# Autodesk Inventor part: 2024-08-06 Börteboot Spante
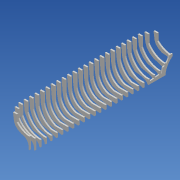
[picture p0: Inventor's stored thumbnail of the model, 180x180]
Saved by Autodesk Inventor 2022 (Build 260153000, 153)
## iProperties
Created: 2024-08
Part Number: 2024-08-06 Börteboot Spante
Material: Generisch
Document SubType Name: Modeling
Designer: i3meg
Density: 1 g/cm^3
Appearance: Vorgabe
Author: i3meg
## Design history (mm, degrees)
sketch "Skizze3"
  geometry: L1 (-117.6, 0)-(19.6, 0) reference; L2 (0, -36.667)-(0, 220.005) reference; L3 (-4, 12)-(-4, 0); L4 (0, 0)-(0, 30); L5 (-35, 30)-(0, 30); L6 (-62, 23)-(-78, 41); L7 (-78, 41)-(-86, 62); L8 (-86, 62)-(-90, 83); L9 (-90, 130)-(-78, 130); L10 (-90, 83)-(-90, 130); L11 (-98, 115)-(-98, 105); L12 (-98, 105)-(-90, 105); L13 (-98, 115)-(-78, 115); L14 (-78, 130)-(-78, 90); L15 (-4, 0)-(0, 0); L16 (-4, 12)-(0, 12); L17 (-90, 83)-(-94, 130); L18 (-94, 130)-(-90, 130); A1 r 59.222 centre (-18.855, 86.979) between (-78, 90) and (-35, 30); A2 r 171.355 centre (-1.548, 183.337) between (-62, 23) and (-4, 12)
  constraints: 34 end point, 5 point on line, 4 perpendicular, 4 point on circle, 3 vertical, 2 centre point, 2 horizontal
  dimensions: "d283" = 4 distance between parallel lines of L2 L3; "d514" = 90 distance from line of L2 L8.end; "d519" = 130 distance from line of L1 L9.start; "d527" = 12 distance of L9.start L9.end; "d538" = 10 distance of L11.start L11.end; "d545" = 35 distance from line of L2 L5.start; "d1072" = 83 distance from line of L1 L8.end; "d1132" = 15 distance between parallel lines of L9 L13; "d1133" = 40 distance of L9.end L14.end; "d1134" = 8 distance between parallel lines of L10 L11; "d1143" = 22 distance from line of L12 L8.end (derived); "d1144" = 86 distance from line of L2 L7.end; "d1145" = 78 distance from line of L2 L6.end; "d1146" = 62 distance from line of L2 L6.start; "d1245" = 21 vertical distance of L8.end L7.end; "d1246" = 21 vertical distance of L7.end L6.end; "d1247" = 18 vertical distance of L6.end L6.start; "d1452" = 4 distance of L9.start L17.end
extrude "Extrusion11" new body sketch "Skizze3" stored distance "d616" = 6; taper "d617" = 0 deg
pattern_linear "Rechteckige Anordnung3" dims "d675" = 23
workplane "Arbeitsebene5"
sketch "Skizze25"
  geometry: L1 (-60, -6)-(-77, 12); L2 (-77, 12)-(-85.5, 33); L3 (-35, 0)-(0, 0); L4 (-85.5, 33)-(-90, 54); L5 (-98, 75)-(-90, 75); L6 (-98, 85)-(-98, 75); L7 (-98, 85)-(-82, 85); L8 (-90, 100)-(-78, 100); L9 (-90, 54)-(-90, 100); L10 (-78, 100)-(-78, 60); L11 (-4, -18)-(-4, -30); L12 (-4, -30)-(0, -30); L13 (0, -30)-(0, 0); L14 (-4, -18)-(0, -18); L15 (-122.858, -30)-(51.151, -30) reference; L16 (0, -88.006)-(0, 318.037) reference; L17 (-90, 54)-(-94, 100); L18 (-94, 100)-(-90, 100); A1 r 66.906 centre (-11.141, 62.507) between (-78, 60) and (-35, 0); A2 r 279.676 centre (26.292, 260.031) between (-60, -6) and (-4, -18)
  constraints: 34 end point, 4 point on circle, 4 point on line, 3 vertical, 2 centre point, 2 horizontal, 2 perpendicular
  dimensions: "d1150" = 12 distance of L8.start L8.end; "d1151" = 10 distance of L6.start L5.start; "d1152" = 15 distance between parallel lines of L8 L7; "d1153" = 40 distance of L8.end L10.end; "d1154" = 8 distance between parallel lines of L9 L6; "d1157" = 77 distance from line of L16 L1.end; "d1158" = 85.5 distance from line of L16 L2.end; "d1159" = 90 distance from line of L16 L4.end; "d1160" = 4 distance between parallel lines of L13 L11; "d1161" = 30 distance between parallel lines of L15 L3; "d1162" = 18 distance between parallel lines of L14 L3; "d1165" = 84 distance from line of L15 L4.end; "d1239" = 35 distance from line of L13 L3.start; "d1241" = 21 vertical distance of L2.end L4.end; "d1242" = 21 vertical distance of L2.end L1.end; "d1243" = 18 vertical distance of L1.start L1.end; "d1244" = 130 distance between parallel lines of L15 L8; "d1453" = 4 distance of L17.end L8.start; "d2116" = 60 distance from line of L16 L1.start
extrude "Extrusion24" join sketch "Skizze25" distance "d1163" = 6; taper "d1164" = 0 deg
workplane "Arbeitsebene14"
sketch "Skizze26"
  geometry: L1 (-85, 34)-(-90, 55); L2 (-76, 14)-(-85, 34); L3 (-60, -4)-(-76, 14); L4 (-30, 0)-(0, 0); L5 (-98, 85)-(-98, 75); L6 (-4, -18)-(0, -18); L7 (-4, -18)-(-4, -30); L8 (-4, -30)-(0, -30); L9 (0, -30)-(0, 0); L10 (-90, 100)-(-78, 100); L11 (-78, 100)-(-78, 60); L12 (-90, 55)-(-90, 100); L13 (-98, 75)-(-90, 75); L14 (-98, 85)-(-82, 85); L15 (-132.187, -30)-(107.122, -30) reference; L16 (0, -117.748)-(0, 496.487) reference; L17 (-90, 55)-(-94, 100); L18 (-94, 100)-(-90, 100); A1 r 433.619 centre (72.935, 408.739) between (-60, -4) and (-4, -18); A2 r 81.932 centre (2.509, 75.207) between (-78, 60) and (-30, 0)
  constraints: 34 end point, 4 point on circle, 4 point on line, 3 vertical, 2 centre point, 2 horizontal, 2 perpendicular
  dimensions: "d1170" = 12 distance of L10.start L10.end; "d1171" = 10 distance of L5.start L5.end; "d1172" = 15 distance between parallel lines of L10 L14; "d1173" = 40 distance of L10.end L11.end; "d1174" = 8 distance between parallel lines of L12 L5; "d1176" = 4 distance between parallel lines of L9 L7; "d1177" = 18 distance between parallel lines of L6 L4; "d1178" = 30 distance from line of L15 L4.end; "d1180" = 76 distance from line of L16 L2.start; "d1181" = 85 distance from line of L16 L1.start; "d1182" = 90 distance from line of L16 L1.end; "d1183" = 130 distance between parallel lines of L15 L10; "d1185" = 30 distance of L4.start L4.end; "d1186" = 45 distance of L10.start L1.end; "d1248" = 21 vertical distance of L1.end L1.start; "d1249" = 20 vertical distance of L2.start L1.start; "d1250" = 18 vertical distance of L3.start L2.start; "d1251" = 60 distance from line of L16 L3.start; "d1454" = 4 distance of L17.end L10.start
extrude "Extrusion25" join sketch "Skizze26" distance "d1190" = 6; taper "d1191" = 0 deg
workplane "Arbeitsebene17"
sketch "Skizze30"
  geometry: L1 (-84.5, 36)-(-90, 56); L2 (-74, 16)-(-84.5, 36); L3 (-59, -1)-(-74, 16); L4 (-24, 1)-(0, 1); L5 (-98, 85)-(-98, 75); L6 (-4, -18)-(0, -18); L7 (-4, -18)-(-4, -30); L8 (-4, -30)-(0, -30); L9 (0, -30)-(0, 1); L10 (-90, 100)-(-78, 100); L11 (-78, 100)-(-78, 60); L12 (-90, 56)-(-90, 100); L13 (-98, 75)-(-90, 75); L14 (-98, 85)-(-82, 85); L15 (-117.95, -30)-(21.701, -30) reference; L16 (0, -281.22)-(0, 163.537) reference; L17 (-90, 56)-(-94, 100); L18 (-94, 100)-(-90, 100); A1 r 81.932 centre (1.751, 78.781) between (-78, 60) and (-24, 1); A2 r 219.794 centre (-95.847, -217.683) between (-4, -18) and (-59, -1)
  constraints: 34 end point, 4 point on circle, 3 vertical, 2 centre point, 2 perpendicular, 2 point on line, 1 horizontal
  dimensions: "d1279" = 12 distance of L10.start L10.end; "d1280" = 10 distance of L5.start L5.end; "d1281" = 15 distance between parallel lines of L10 L14; "d1282" = 40 distance of L10.end L11.end; "d1283" = 8 distance between parallel lines of L12 L5; "d1284" = 4 distance between parallel lines of L9 L7; "d1285" = 19 distance between parallel lines of L6 L4; "d1291" = 24 distance of L4.start L4.end; "d1292" = 44 distance of L10.start L1.end; "d1293" = 20 vertical distance of L1.end L1.start; "d1294" = 20 vertical distance of L2.start L1.start; "d1295" = 17 vertical distance of L3.start L2.start; "d1298" = 130 distance between parallel lines of L15 L10; "d1345" = 90 distance between parallel lines of L16 L12; "d1346" = 31 distance between parallel lines of L15 L4; "d1423" = 59 distance from line of L16 L3.start; "d1455" = 4 distance of L17.end L10.start; "d1475" = 84.5 distance from line of L16 L1.start; "d2117" = 74 distance from line of L16 L2.start
extrude "Extrusion30" join sketch "Skizze30" distance "d1300" = 6; taper "d1301" = 0 deg
workplane "Arbeitsebene18"
sketch "Skizze31"
  geometry: L1 (-84, 38)-(-90, 57); L2 (-73, 19)-(-84, 38); L3 (-58, 3)-(-73, 19); L4 (-15, 2)-(0, 2); L5 (-98, 85)-(-98, 75); L6 (-4, -18)-(0, -18); L7 (-4, -18)-(-4, -30); L8 (-4, -30)-(0, -30); L9 (0, -30)-(0, 2); L10 (-90, 100)-(-78, 100); L11 (-78, 100)-(-78, 60); L12 (-90, 57)-(-90, 100); L13 (-98, 75)-(-90, 75); L14 (-98, 85)-(-82, 85); L15 (-117.763, -30)-(20.576, -30) reference; L16 (0, -56)-(0, 126) reference; L17 (-58, 3)-(-29.474, -1); L18 (-29.474, -1)-(-10, -4); L19 (-10, -4)-(-4, -18); L20 (-90, 57)-(-94, 100); L21 (-94, 100)-(-90, 100); A1 r 81.932 centre (0.813, 82.392) between (-78, 60) and (-15, 2)
  constraints: 34 end point, 3 vertical, 2 horizontal, 2 perpendicular, 2 point on circle, 2 point on line, 1 centre point, 3 other
  dimensions: "d1303" = 12 distance of L10.start L10.end; "d1304" = 10 distance of L5.start L5.end; "d1305" = 15 distance between parallel lines of L10 L14; "d1306" = 40 distance of L10.end L11.end; "d1307" = 8 distance between parallel lines of L12 L5; "d1308" = 4 distance between parallel lines of L9 L7; "d1309" = 20 distance between parallel lines of L6 L4; "d1311" = 43 distance of L10.start L1.end; "d1318" = 90 distance between parallel lines of L16 L12; "d1319" = 32 distance between parallel lines of L15 L4; "d1320" = 130 distance between parallel lines of L15 L10; "d1421" = 10 distance from line of L16 L18.end; "d1422" = 26 distance from line of L15 L18.end; "d1458" = 4 distance of L20.end L10.start; "d1471" = 19 vertical distance of L2.start L1.start; "d1472" = 19 vertical distance of L1.start L1.end; "d1473" = 16 vertical distance of L2.start L3.start; "d2101" = 84 distance from line of L16 L1.start; "d2114" = 58 distance from line of L16 L3.start; "d2115" = 73 distance from line of L16 L2.start
extrude "Extrusion31" join sketch "Skizze31" distance "d1321" = 6; taper "d1322" = 0 deg
workplane "Arbeitsebene19"
sketch "Skizze32"
  geometry: L1 (-83, 40)-(-90, 58); L2 (-72, 22)-(-83, 40); L3 (-55, 7)-(-72, 22); L4 (-10, 6)-(0, 6); L5 (-98, 85)-(-98, 75); L6 (-4, -18)-(0, -18); L7 (-4, -18)-(-4, -30); L8 (-4, -30)-(0, -30); L9 (0, -30)-(0, 6); L10 (-90, 100)-(-78, 100); L11 (-78, 100)-(-78, 60); L12 (-90, 58)-(-90, 100); L13 (-98, 75)-(-90, 75); L14 (-98, 85)-(-82, 85); L15 (-117.674, -30)-(20.044, -30) reference; L16 (0, -56)-(0, 126) reference; L17 (-55, 7)-(-13, -2.108); L18 (-13, -2.108)-(-7, -2); L19 (-7, -2)-(-4, -18); L20 (-90, 58)-(-94, 100); L21 (-94, 100)-(-90, 100); A1 r 81.932 centre (-0.79, 87.413) between (-78, 60) and (-10, 6)
  constraints: 34 end point, 3 vertical, 2 horizontal, 2 perpendicular, 2 point on circle, 2 point on line, 1 centre point, 3 other
  dimensions: "d1324" = 12 distance of L10.start L10.end; "d1325" = 10 distance of L5.start L5.end; "d1326" = 15 distance between parallel lines of L10 L14; "d1327" = 40 distance of L10.end L11.end; "d1328" = 8 distance between parallel lines of L12 L5; "d1329" = 4 distance between parallel lines of L9 L7; "d1330" = 24 distance between parallel lines of L6 L4; "d1331" = 10 distance of L4.start L4.end; "d1332" = 42 distance of L10.start L1.end; "d1339" = 36 distance between parallel lines of L15 L4; "d1341" = 130 distance between parallel lines of L15 L10; "d1407" = 7 distance from line of L9 L18.end; "d1408" = 28 distance from line of L15 L18.end; "d1409" = 13 distance from line of L16 L17.end; "d1413" = 72 distance from line of L16 L2.start; "d1414" = 18 vertical distance of L1.start L1.end; "d1415" = 18 vertical distance of L2.start L1.start; "d1416" = 15 vertical distance of L3.start L2.start; "d1420" = 83 distance from line of L16 L1.start; "d1459" = 4 distance of L20.end L10.start; "d2102" = 90 distance between parallel lines of L16 L12
extrude "Extrusion32" join sketch "Skizze32" distance "d1342" = 6; taper "d1343" = 0 deg
workplane "Arbeitsebene20"
sketch "Skizze33"
  geometry: L1 (-82, 43)-(-88, 61); L2 (-70, 26)-(-82, 43); L3 (-52, 12)-(-70, 26); L4 (-10, 10)-(0, 10); L5 (-96, 85)-(-96, 75); L6 (-4, -8)-(0, -8); L7 (-4, -8)-(-4, -30); L8 (-4, -30)-(0, -30); L9 (0, -30)-(0, 10); L10 (-88, 100)-(-76, 100); L11 (-76, 100)-(-76, 60); L12 (-88, 61)-(-88, 100); L13 (-96, 75)-(-88, 75); L14 (-96, 85)-(-82, 85); L15 (-115.2, -30)-(19.2, -30) reference; L16 (0, -56)-(0, 126) reference; L17 (-52, 12)-(-20, 5); L18 (-20, 5)-(-7, 0); L19 (-7, 0)-(-4, -8); L20 (-88, 61)-(-92, 100); L21 (-92, 100)-(-88, 100); A1 r 81.932 centre (-0.305, 91.357) between (-76, 60) and (-10, 10); 1 further point
  constraints: 34 end point, 3 point on line, 3 vertical, 2 horizontal, 2 perpendicular, 2 point on circle, 1 centre point, 3 other
  dimensions: "d1348" = 12 distance of L10.start L10.end; "d1349" = 10 distance of L5.start L5.end; "d1350" = 15 distance between parallel lines of L10 L14; "d1351" = 40 distance of L10.end L11.end; "d1352" = 8 distance between parallel lines of L12 L5; "d1353" = 4 distance between parallel lines of L9 L7; "d1354" = 18 distance between parallel lines of L6 L4; "d1355" = 10 distance of L4.start L4.end; "d1356" = 39 distance of L10.start L1.end; "d1357" = 18 vertical distance of L1.end L1.start; "d1358" = 17 vertical distance of L2.start L1.start; "d1364" = 40 distance between parallel lines of L15 L4; "d1365" = 130 distance between parallel lines of L15 L10; "d1396" = 14 vertical distance of L2.start L3.start; "d1399" = 88 distance between parallel lines of L12 L16; "d1402" = 7 distance from line of L9 L18.end; "d1403" = 30 distance from line of L15 L18.end; "d1410" = 35 distance from line of L15 L17.end; "d1411" = 20 distance from line of L16 L17.end; "d1412" = 70 distance from line of L16 L2.start; "d1417" = 52 distance from line of L16 L3.start; "d1460" = 4 distance of L20.end L10.start; "d2118" = 82 distance from line of L16 L1.start
extrude "Extrusion33" join sketch "Skizze33" distance "d1366" = 6; taper "d1367" = 0 deg
workplane "Arbeitsebene21"
sketch "Skizze34"
  geometry: L1 (-112.834, -30)-(19.003, -30) reference; L2 (0, -57.46)-(0, 134.759) reference; L3 (-76, 48)-(-82, 65); L4 (-63.388, 33)-(-76, 48); L5 (-10, 26)-(0, 26); L6 (-90, 85)-(-90, 75); L7 (-4, 8)-(0, 8); L8 (-4, 8)-(-4, -4); L9 (-4, -4)-(0, -4); L10 (0, -4)-(0, 26); L11 (-82, 100)-(-70, 100); L12 (-70, 100)-(-70, 65); L13 (-82, 65)-(-82, 100); L14 (-90, 75)-(-82, 75); L15 (-90, 85)-(-82, 85); L16 (-4, 8)-(-6.652, 5.448); L17 (-45, 21)-(-63.388, 33); L18 (-6.652, 5.448)-(-12.18, 14.581); L19 (-12.18, 14.581)-(-45, 21); L20 (-82, 65)-(-86, 100); L21 (-86, 100)-(-82, 100); A1 r 81.932 centre (0.169, 107.299) between (-70, 65) and (-10, 26); 5 further points
  constraints: 34 end point, 3 vertical, 2 horizontal, 2 perpendicular, 2 point on circle, 2 point on line, 1 centre point, 3 other
  dimensions: "d1369" = 12 distance of L11.start L11.end; "d1370" = 10 distance of L6.start L6.end; "d1371" = 15 distance between parallel lines of L11 L15; "d1372" = 35 distance of L11.end L12.end; "d1373" = 8 distance between parallel lines of L13 L6; "d1374" = 4 distance between parallel lines of L10 L8; "d1375" = 18 distance between parallel lines of L7 L5; "d1376" = 10 distance of L5.start L5.end; "d1377" = 35 distance of L11.start L3.end; "d1378" = 17 vertical distance of L3.end L3.start; "d1379" = 15 vertical distance of L4.start L3.start; "d1384" = 82 distance between parallel lines of L2 L13; "d1385" = 56 distance between parallel lines of L1 L5; "d1386" = 130 distance between parallel lines of L1 L11; "d1451" = 12 vertical distance of L17.start L4.start; "d1461" = 4 distance of L20.end L11.start; "d1474" = 45 distance from line of L2 L17.start
extrude "Extrusion35" join sketch "Skizze34" distance "d1389" = 6; taper "d1390" = 0 deg
workplane "Arbeitsebene22"
sketch "Skizze35"
  geometry: L1 (-61.305, 57)-(-66, 70); L2 (-50.126, 46)-(-61.305, 57); L3 (-35, 38)-(-50.126, 46); L4 (-10, 47)-(0, 47); L5 (-74, 85)-(-74, 75); L6 (-4, 31)-(0, 31); L7 (-4, 31)-(-4, 15); L8 (-4, 15)-(0, 15); L9 (0, 15)-(0, 47); L10 (-66, 100)-(-54, 100); L11 (-54, 100)-(-54, 70); L12 (-66, 70)-(-66, 100); L13 (-74, 75)-(-66, 75); L14 (-74, 85)-(-82, 85); L15 (-4, 31)-(-4, 35.985); L16 (-4, 35.985)-(-12.319, 35.985); L17 (-12.319, 35.985)-(-35, 38); L18 (-66, 70)-(-70, 100); L19 (-70, 100)-(-66, 100); A1 r 81.932 centre (4.171, 127.698) between (-54, 70) and (-10, 47); 13 further points
  constraints: 35 end point, 3 vertical, 2 horizontal, 2 perpendicular, 2 point on circle, 1 centre point, 1 midpoint, 1 point on line, 5 other
  dimensions: "d1425" = 12 distance of L10.start L10.end; "d1426" = 10 distance of L5.start L5.end; "d1427" = 15 distance between parallel lines of L10 L14; "d1428" = 30 distance of L10.end L11.end; "d1429" = 8 distance between parallel lines of L12 L5; "d1430" = 4 distance between parallel lines of L9 L7; "d1431" = 16 distance between parallel lines of L6 L4; "d1432" = 10 distance of L4.start L4.end; "d1433" = 30 distance of L10.start L1.end; "d1434" = 13 vertical distance of L1.end L1.start; "d1435" = 11 vertical distance of L2.start L1.start; "d1445" = 77 dimension on L4; "d1446" = 66 distance of the line from the sketch origin of L12; "d1447" = 8 vertical distance of L2.start L3.start; "d1450" = 130 dimension on L10; "d1462" = 4 distance of L18.end L10.start; "d1970" = 35 dimension on L3.start
extrude "Extrusion36" join sketch "Skizze35" distance "d1448" = 6; taper "d1449" = 0 deg
workplane "Arbeitsebene26"
sketch "Skizze43"
  geometry: L1 (-26.579, -7)-(-43, 12); L2 (-43, 12)-(-50.5, 33); L3 (0, 0)-(35, 0); L4 (-50.5, 33)-(-55, 54); L5 (-63, 75)-(-55, 75); L6 (-63, 85)-(-63, 75); L7 (-63, 85)-(-47, 85); L8 (-55, 100)-(-43, 100); L9 (-55, 54)-(-55, 100); L10 (-43, 100)-(-43, 60); L11 (31, -18)-(31, -30); L12 (31, -30)-(35, -30); L13 (35, -30)-(35, 0); L14 (31, -18)-(35, -18); L15 (-55, 54)-(-59, 100); L16 (-59, 100)-(-55, 100); L17 (-86.48, -30)-(77.882, -30) reference; L18 (35, -88.139)-(35, 318.834) reference; A1 r 66.906 centre (23.859, 62.507) between (-43, 60) and (0, 0); A2 r 279.676 centre (54.402, 260.695) between (-26.579, -7) and (31, -18); 1 further point
  constraints: 34 end point, 4 point on circle, 3 point on line, 3 vertical, 2 centre point, 2 horizontal, 2 perpendicular
  dimensions: "d1538" = 12 distance of L8.start L8.end; "d1539" = 10 distance of L6.start L5.start; "d1540" = 15 distance between parallel lines of L8 L7; "d1541" = 40 distance of L8.end L10.end; "d1542" = 8 distance between parallel lines of L9 L6; "d1546" = 4 distance between parallel lines of L13 L11; "d1548" = 18 distance between parallel lines of L14 L3; "d1550" = 35 distance from line of L13 L3.start; "d1551" = 21 vertical distance of L2.end L4.end; "d1552" = 21 vertical distance of L2.end L1.end; "d1553" = 19 vertical distance of L1.start L1.end; "d1555" = 4 distance of L15.end L8.start; "d2103" = 90 distance between parallel lines of L18 L9; "d2104" = 85.5 distance from line of L18 L2.end; "d2119" = 78 distance from line of L18 L1.end
extrude "Extrusion41" join sketch "Skizze43" distance "d1556" = 6; taper "d1557" = 0 deg
workplane "Arbeitsebene27"
sketch "Skizze44"
  geometry: L1 (-50, 34)-(-55, 55); L2 (-42, 14)-(-50, 34); L3 (-26, -5)-(-42, 14); L4 (5, 0)-(35, 0); L5 (-63, 85)-(-63, 75); L6 (31, -18)-(35, -18); L7 (31, -18)-(31, -30); L8 (31, -30)-(35, -30); L9 (35, -30)-(35, 0); L10 (-55, 100)-(-43, 100); L11 (-43, 100)-(-43, 60); L12 (-55, 55)-(-55, 100); L13 (-63, 75)-(-55, 75); L14 (-63, 85)-(-47, 85); L15 (-55, 55)-(-59, 100); L16 (-59, 100)-(-55, 100); L17 (-95.34, -30)-(131.04, -30) reference; L18 (35, -118.06)-(35, 498.362) reference; A1 r 433.619 centre (98.7, 410.301) between (-26, -5) and (31, -18); A2 r 81.932 centre (37.509, 75.207) between (-43, 60) and (5, 0); 1 further point
  constraints: 34 end point, 4 point on circle, 3 vertical, 2 centre point, 2 horizontal, 2 perpendicular, 2 point on line
  dimensions: "d1559" = 12 distance of L10.start L10.end; "d1560" = 10 distance of L5.start L5.end; "d1561" = 15 distance between parallel lines of L10 L14; "d1562" = 40 distance of L10.end L11.end; "d1563" = 8 distance between parallel lines of L12 L5; "d1564" = 4 distance between parallel lines of L9 L7; "d1565" = 18 distance between parallel lines of L6 L4; "d1571" = 30 distance of L4.start L4.end; "d1572" = 45 distance of L10.start L1.end; "d1573" = 21 vertical distance of L1.end L1.start; "d1574" = 20 vertical distance of L2.start L1.start; "d1575" = 19 vertical distance of L3.start L2.start; "d1577" = 4 distance of L15.end L10.start; "d2105" = 90 distance between parallel lines of L18 L12; "d2106" = 85 distance from line of L18 L1.start; "d2120" = 77 distance from line of L18 L2.start
extrude "Extrusion42" join sketch "Skizze44" distance "d1578" = 6; taper "d1579" = 0 deg
workplane "Arbeitsebene28"
sketch "Skizze49"
  geometry: L1 (-49.5, 36)-(-55, 56); L2 (-40, 16)-(-49.5, 36); L3 (-25, -1)-(-40, 16); L4 (11, 1)-(35, 1); L5 (-63, 85)-(-63, 75); L6 (31, -18)-(35, -18); L7 (31, -18)-(31, -30); L8 (31, -30)-(35, -30); L9 (35, -30)-(35, 1); L10 (-55, 100)-(-43, 100); L11 (-43, 100)-(-43, 60); L12 (-55, 56)-(-55, 100); L13 (-63, 75)-(-55, 75); L14 (-63, 85)-(-47, 85); L15 (-55, 56)-(-59, 100); L16 (-59, 100)-(-55, 100); L17 (-82.95, -30)-(56.701, -30) reference; L18 (35, -281.533)-(35, 163.589) reference; A1 r 81.932 centre (36.751, 78.781) between (-43, 60) and (11, 1); A2 r 219.794 centre (-60.278, -217.944) between (31, -18) and (-25, -1); 1 further point
  constraints: 34 end point, 4 point on circle, 3 vertical, 2 centre point, 2 perpendicular, 2 point on line, 1 horizontal
  dimensions: "d1658" = 12 distance of L10.start L10.end; "d1659" = 10 distance of L5.start L5.end; "d1660" = 15 distance between parallel lines of L10 L14; "d1661" = 40 distance of L10.end L11.end; "d1662" = 8 distance between parallel lines of L12 L5; "d1663" = 4 distance between parallel lines of L9 L7; "d1664" = 19 distance between parallel lines of L6 L4; "d1665" = 24 distance of L4.start L4.end; "d1666" = 44 distance of L10.start L1.end; "d1667" = 20 vertical distance of L1.end L1.start; "d1668" = 20 vertical distance of L2.start L1.start; "d1669" = 17 vertical distance of L3.start L2.start; "d1674" = 4 distance of L15.end L10.start; "d2107" = 90 distance between parallel lines of L18 L12; "d2108" = 84.5 distance from line of L18 L1.start; "d2121" = 75 distance from line of L18 L2.start
extrude "Extrusion46" join sketch "Skizze49" distance "d1676" = 6; taper "d1677" = 0 deg
workplane "Arbeitsebene31"
sketch "Skizze51"
  geometry: L1 (-48, 38)-(-55, 57); L2 (-38, 19)-(-48, 38); L3 (-23, 3)-(-38, 19); L4 (20, 2)-(35, 2); L5 (-63, 85)-(-63, 75); L6 (31, -18)-(35, -18); L7 (31, -18)-(31, -30); L8 (31, -30)-(35, -30); L9 (35, -30)-(35, 2); L10 (-55, 100)-(-43, 100); L11 (-43, 100)-(-43, 60); L12 (-55, 57)-(-55, 100); L13 (-63, 75)-(-55, 75); L14 (-63, 85)-(-47, 85); L15 (-23, 3)-(1.526, -1); L16 (1.526, -1)-(25, -4); L17 (25, -4)-(31, -18); L18 (-55, 57)-(-59, 100); L19 (-59, 100)-(-55, 100); L20 (-82.763, -30)-(55.576, -30) reference; L21 (35, -56)-(35, 126) reference; A1 r 81.932 centre (35.813, 82.392) between (-43, 60) and (20, 2); 1 further point
  constraints: 34 end point, 3 vertical, 2 horizontal, 2 perpendicular, 2 point on circle, 2 point on line, 1 centre point, 3 other
  dimensions: "d1697" = 12 distance of L10.start L10.end; "d1698" = 10 distance of L5.start L5.end; "d1699" = 15 distance between parallel lines of L10 L14; "d1700" = 40 distance of L10.end L11.end; "d1701" = 8 distance between parallel lines of L12 L5; "d1702" = 4 distance between parallel lines of L9 L7; "d1703" = 20 distance between parallel lines of L6 L4; "d1704" = 43 distance of L10.start L1.end; "d1710" = 4 distance of L18.end L10.start; "d1711" = 19 vertical distance of L2.start L1.start; "d1712" = 19 vertical distance of L1.start L1.end; "d1713" = 16 vertical distance of L2.start L3.start; "d2109" = 90 distance between parallel lines of L21 L12; "d2110" = 83 distance from line of L21 L1.start; "d2122" = 73 distance from line of L21 L2.start
extrude "Extrusion47" join sketch "Skizze51" distance "d1714" = 6; taper "d1715" = 0 deg
workplane "Arbeitsebene32"
sketch "Skizze52"
  geometry: L1 (-46, 40)-(-55, 58); L2 (-35, 22)-(-46, 40); L3 (-20, 7)-(-35, 22); L4 (25, 6)-(35, 6); L5 (-63, 85)-(-63, 75); L6 (31, -18)-(35, -18); L7 (31, -18)-(31, -30); L8 (31, -30)-(35, -30); L9 (35, -30)-(35, 6); L10 (-55, 100)-(-43, 100); L11 (-43, 100)-(-43, 60); L12 (-55, 58)-(-55, 100); L13 (-63, 75)-(-55, 75); L14 (-63, 85)-(-47, 85); L15 (-20, 7)-(22, -2.108); L16 (22, -2.108)-(28, -2); L17 (28, -2)-(31, -18); L18 (-55, 58)-(-59, 100); L19 (-59, 100)-(-55, 100); L20 (-82.674, -30)-(55.044, -30) reference; L21 (35, -56)-(35, 126) reference; A1 r 81.932 centre (34.21, 87.413) between (-43, 60) and (25, 6); 1 further point
  constraints: 34 end point, 3 vertical, 2 horizontal, 2 perpendicular, 2 point on circle, 2 point on line, 1 centre point, 3 other
  dimensions: "d1717" = 12 distance of L10.start L10.end; "d1718" = 10 distance of L5.start L5.end; "d1719" = 15 distance between parallel lines of L10 L14; "d1720" = 40 distance of L10.end L11.end; "d1721" = 8 distance between parallel lines of L12 L5; "d1722" = 4 distance between parallel lines of L9 L7; "d1723" = 24 distance between parallel lines of L6 L4; "d1724" = 10 distance of L4.start L4.end; "d1725" = 42 distance of L10.start L1.end; "d1728" = 7 distance from line of L9 L16.end; "d1732" = 18 vertical distance of L1.start L1.end; "d1733" = 18 vertical distance of L2.start L1.start; "d1734" = 15 horizontal distance of L3.start L2.start; "d1736" = 4 distance of L18.end L10.start; "d2111" = 90 distance between parallel lines of L21 L12; "d2112" = 81 distance from line of L21 L1.start; "d2123" = 70 distance from line of L21 L2.start
extrude "Extrusion48" join sketch "Skizze52" distance "d1737" = 6; taper "d1738" = 0 deg
workplane "Arbeitsebene33"
sketch "Skizze53"
  geometry: L1 (-45, 43)-(-55, 61); L2 (-32, 26)-(-45, 43); L3 (-17, 12)-(-32, 26); L4 (25, 10)-(35, 10); L5 (-63, 85)-(-63, 75); L6 (31, -18)-(35, -18); L7 (31, -18)-(31, -30); L8 (31, -30)-(35, -30); L9 (35, -30)-(35, 10); L10 (-55, 100)-(-43, 100); L11 (-43, 100)-(-43, 60); L12 (-55, 61)-(-55, 100); L13 (-63, 75)-(-55, 75); L14 (-63, 85)-(-47, 85); L15 (-17, 12)-(15, 5); L16 (15, 5)-(28, 0); L17 (28, 0)-(31, -18); L18 (-55, 61)-(-59, 100); L19 (-59, 100)-(-55, 100); L20 (-82.91, -30)-(56.46, -30) reference; L21 (35, -56)-(35, 126) reference; A1 r 81.932 centre (32.602, 91.579) between (-43, 60) and (25, 10); 2 further points
  constraints: 34 end point, 3 vertical, 2 horizontal, 2 perpendicular, 2 point on circle, 2 point on line, 1 centre point, 3 other
  dimensions: "d1740" = 12 distance of L10.start L10.end; "d1741" = 10 distance of L5.start L5.end; "d1742" = 15 distance between parallel lines of L10 L14; "d1743" = 40 distance of L10.end L11.end; "d1744" = 8 distance between parallel lines of L12 L5; "d1745" = 4 distance between parallel lines of L9 L7; "d1746" = 28 distance between parallel lines of L6 L4; "d1747" = 10 distance of L4.start L4.end; "d1748" = 39 distance of L10.start L1.end; "d1749" = 18 vertical distance of L1.end L1.start; "d1750" = 17 vertical distance of L2.start L1.start; "d1753" = 14 vertical distance of L2.start L3.start; "d1755" = 7 distance from line of L9 L16.end; "d1761" = 4 distance of L18.end L10.start; "d2113" = 90 distance between parallel lines of L21 L12; "d2124" = 80 distance from line of L21 L1.start; "d2125" = 67 distance from line of L21 L2.start
extrude "Extrusion49" join sketch "Skizze53" distance "d1762" = 6; taper "d1763" = 0 deg
workplane "Arbeitsebene38"
sketch "Skizze62"
  geometry: L1 (-78.677, -30)-(59.06, -30) reference; L2 (35, -57.46)-(35, 134.759) reference; L3 (30.709, 26)-(39.383, 26); L4 (-41, 48)-(-47, 65); L5 (-28.388, 33)-(-41, 48); L6 (25, 26)-(35, 26); L7 (-55, 85)-(-55, 75); L8 (31, -6)-(35, -6); L9 (31, -6)-(31, -18); L10 (31, -18)-(35, -18); L11 (35, -18)-(35, 26); L12 (-47, 100)-(-35, 100); L13 (-35, 100)-(-35, 65); L14 (-47, 65)-(-47, 100); L15 (-55, 75)-(-47, 75); L16 (-55, 85)-(-47, 85); L17 (31, -6)-(28.348, 5.448); L18 (28.348, 5.448)-(22.82, 14.581); L19 (22.82, 14.581)-(-10, 21); L20 (-10, 21)-(-28.388, 33); L21 (-47, 65)-(-51, 100); L22 (-51, 100)-(-47, 100); A1 r 81.932 centre (35.169, 107.299) between (-35, 65) and (25, 26); 9 further points
  constraints: 36 end point, 4 point on line, 3 perpendicular, 3 vertical, 2 horizontal, 2 point on circle, 1 centre point, 3 other
  dimensions: "d1893" = 56 distance between parallel lines of L1 L3; "d1894" = 12 distance of L12.start L12.end; "d1895" = 10 distance of L7.start L7.end; "d1896" = 15 distance between parallel lines of L12 L16; "d1897" = 35 distance of L12.end L13.end; "d1898" = 8 distance between parallel lines of L14 L7; "d1899" = 4 distance between parallel lines of L11 L9; "d1900" = 32 distance between parallel lines of L8 L6; "d1901" = 10 distance of L6.start L6.end; "d1902" = 35 distance of L12.start L4.end; "d1903" = 17 vertical distance of L4.end L4.start; "d1904" = 15 vertical distance of L5.start L4.start; "d1908" = 12 vertical distance of L19.end L5.start; "d1909" = 4 distance of L21.end L12.start
extrude "Extrusion51" join sketch "Skizze62" distance "d1911" = 6; taper "d1912" = 0 deg
workplane "Arbeitsebene39"
sketch "Skizze63"
  geometry: L1 (-26.305, 57)-(-31, 70); L2 (-15.126, 46)-(-26.305, 57); L3 (0.729, 38)-(-15.126, 46); L4 (25, 45)-(35, 45); L5 (-39, 85)-(-39, 75); L6 (31, 9.18)-(31, -5); L7 (31, -5)-(35, -5); L8 (35, -5)-(35, 45); L9 (-31, 100)-(-19, 100); L10 (-19, 100)-(-19, 70); L11 (-31, 70)-(-31, 100); L12 (-39, 75)-(-31, 75); L13 (-39, 85)-(-47, 85); L14 (31, 9.18)-(31, 17.696); L15 (31, 17.696)-(22.681, 35.985); L16 (22.681, 35.985)-(0.729, 38); L17 (-31, 70)-(-35, 100); L18 (-35, 100)-(-31, 100); L19 (35, -61.051)-(35, 156.305) reference; L20 (35, 47)-(25, 47) reference; A1 r 81.932 centre (41.497, 125.254) between (-19, 70) and (25, 45); 13 further points; 1 other entity
  constraints: 33 end point, 3 vertical, 2 horizontal, 2 point on circle, 2 point on line, 1 centre point, 1 perpendicular, 4 other
  dimensions: "d1914" = 12 distance of L9.start L9.end; "d1915" = 10 distance of L5.start L5.end; "d1916" = 15 distance between parallel lines of L9 L13; "d1917" = 30 distance of L9.end L10.end; "d1918" = 8 distance between parallel lines of L11 L5; "d1919" = 4 distance between parallel lines of L8 L6; "d1921" = 10 distance of L4.start L4.end; "d1922" = 30 distance of L9.start L1.end; "d1923" = 13 vertical distance of L1.end L1.start; "d1924" = 11 vertical distance of L2.start L1.start; "d1927" = 8 vertical distance of L2.start L3.start; "d1929" = 4 distance of L17.end L9.start; "d1932" = 75 dimension on L4; "d1933" = 50 distance between parallel lines of L7 L4
extrude "Extrusion52" join sketch "Skizze63" distance "d1930" = 6; taper "d1931" = 0 deg
sketch "Skizze92"
  geometry: L1 (-91, -49)-(-97, -49) reference; L2 (-97, -49)-(-25, -49); L3 (-36.177, -15)-(-41, -33); L4 (-41, -33)-(-97, -39); L5 (-97, -39)-(-97, -49); L6 (5, 16)-(5, -5); L7 (5, -5)-(-6, -5); L8 (-10, 16)-(5, 16); L9 (5, 16)-(5, 6); L10 (0, 77.576)-(0, -67.31); L11 (-25, -49)-(47.992, -49); A1 r 35.622 centre (-45.46, 19.391) between (-36.177, -15) and (-10, 16); A2 r 70.036 centre (44.991, -51.495) between (5, 6) and (-25, -49); 3 further points
  constraints: 20 end point, 4 point on circle, 3 horizontal, 2 centre point, 1 perpendicular, 1 point on line, 1 vertical
  dimensions: "d2179" = 10 distance from line of L9.end L8; "d2181" = 25 distance from line of L10 L2.end; "d2182" = 65 distance between parallel lines of L8 L11; "d2183" = 15 distance of L6.start L8.start; "d2184" = 5 distance from line of L10 L6.start; "d2185" = 34 distance from line of L2 L3.start; "d2186" = 16 distance from line of L2 L3.end; "d2188" = 260 horizontal distance of L3.end point (-301, -61); "d2189" = 75 deg angle of L2 L3
extrude "Extrusion63" join sketch "Skizze92" distance "d2175" = 4.5; taper "d2176" = 0 deg
node "Volumenkörper7"
other parameters: "d736" = 23, "d1166" = 23, "d1253" = 23, "d1302" = 23, "d1323" = 23, "d1347" = 23, "d1368" = 22, "d1424" = 23, "d1537" = 23, "d1558" = 23, "d1580" = 23, "d1696" = 23, "d1716" = 23, "d1739" = 23, "d1892" = 23, "d1913" = 23, "d2096" = 3, "d2097" = 3, "d2098" = 3
